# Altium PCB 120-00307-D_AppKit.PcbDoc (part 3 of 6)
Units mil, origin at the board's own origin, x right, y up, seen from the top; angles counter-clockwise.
Board outline 5150 x 3100 mil, 6 copper layers (L1, L2 (GND), L3-SIG, L4-SIG, L5 (PWR), L6), stack 61.956 mil thick; 413 components, 344 nets, 1685 pads, 1021 vias.
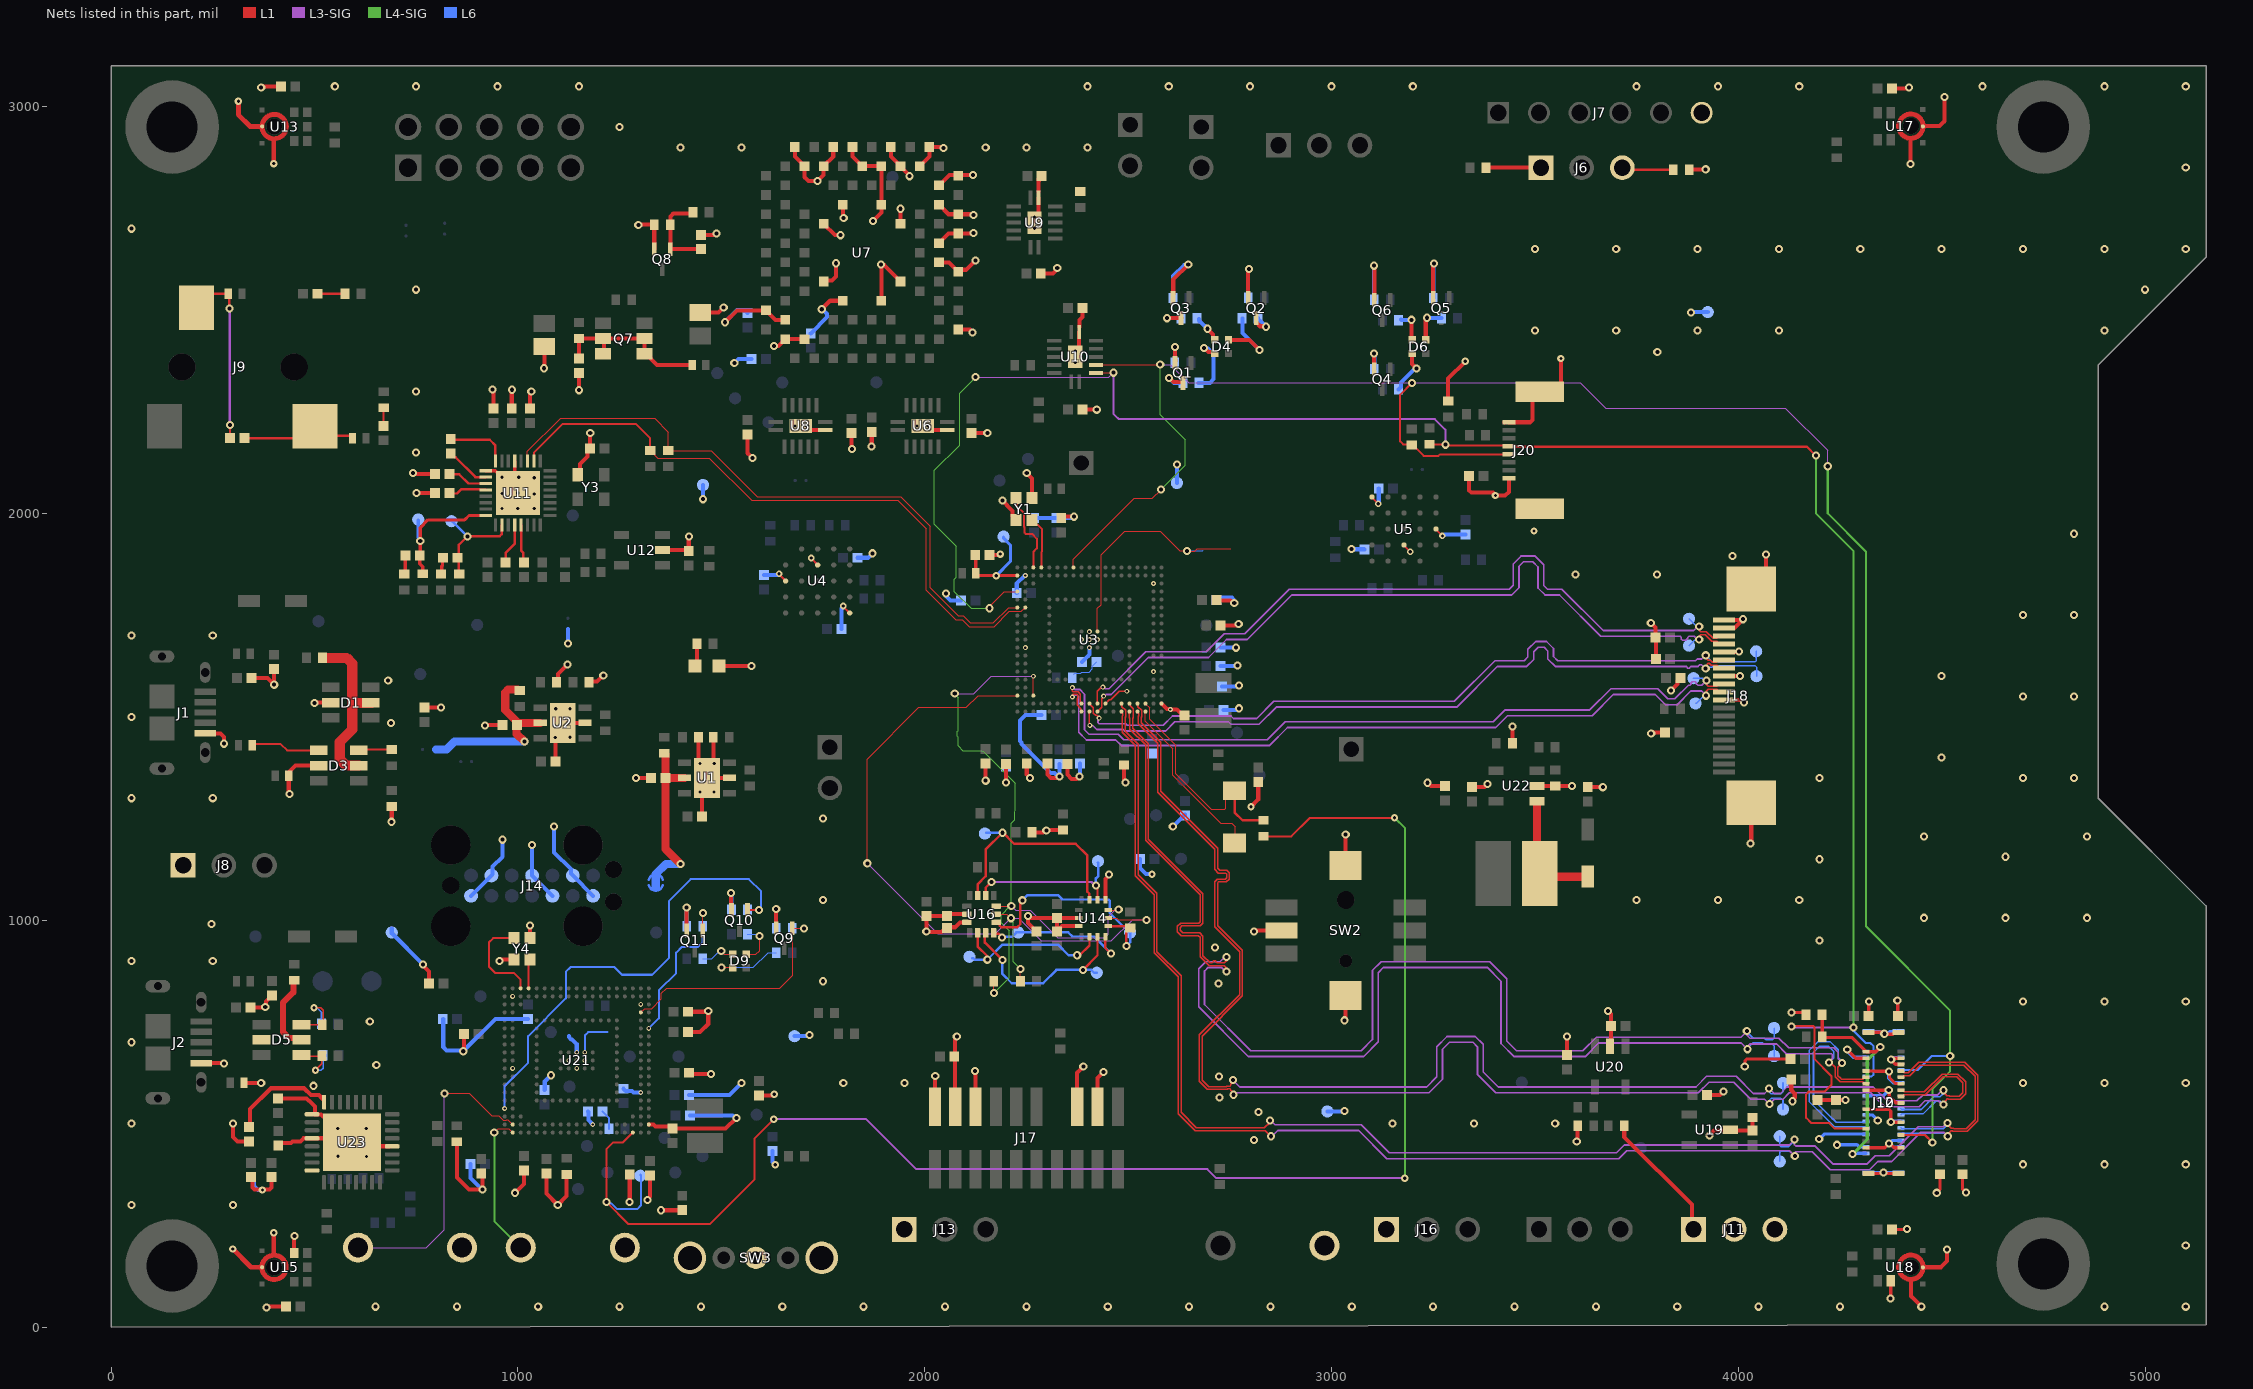
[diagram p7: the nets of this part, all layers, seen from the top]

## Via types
v1: diameter 20, hole 10, L1 to L6, tented both sides, 437 vias
v2: diameter 20, hole 10, L1 to L6, 330 vias
v3: diameter 12, hole 6, L1 to L6, tented both sides, 120 vias
v4: diameter 18, hole 8, L1 to L6, 93 vias
v5: diameter 16, hole 8, L1 to L6, tented both sides, 41 vias

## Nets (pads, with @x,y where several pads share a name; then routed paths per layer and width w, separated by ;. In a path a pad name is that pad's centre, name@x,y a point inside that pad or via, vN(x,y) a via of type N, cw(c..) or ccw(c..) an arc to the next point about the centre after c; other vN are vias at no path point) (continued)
GND: C1.2 C2.1 C3.2 C4.1 C5.1 C6.1 C7.2 C8.2 C9.1 C10.1 C11.1 C12.1 C13.1 C14.1 C15.1 C16.1 C17.1 C18.1 C19.1 C20.1 C21.1 C22.1 C23.1 C24.2 C25.2 C26.2 C27.1 C28.1 C29.1 C30.1 C31.1 C32.1 C33.1 C34.1 C35.1 C36.1 C37.1 C38.1 C39.1 C40.1 C41.1 C42.1 C43.1 C44.2 C45.1 C46.2 C47.1 C48.2 C49.1 C50.1 C51.1 C52.1 C53.1 C54.1 C55.1 C56.2 C57.1 C64.1 C65.1 C66.1 C71.1 C72.1 C73.1 C75.2 C76.1 C77.2 C78.1 C79.2 C80.2 C81.2 C82.2 C83.2 C84.2 C85.1 C86.1 C87.1 C88.1 C89.1 C90.1 C91.1 C92.1 C93.1 C94.1 C95.1 C96.1 C97.1 C98.1 C99.1 C100.1 C101.1 C102.1 C103.1 C104.1 C105.1 C106.1 C107.1 C108.1 C109.2 C110.2 C111.1 C112.1 C113.1 C114.1 C115.1 C116.2 C117.2 C118.2 C119.1 C120.2 C121.1 C122.1 C123.2 C124.2 C125.1 C126.1 C127.1 C128.1 C129.1 C130.1 C131.1 C132.1 C133.1 C134.1 C141.1 D1.2 D2.K D3.2 D5.2 FB3.2 FB5.2 J1.5 J2.5 J7.6 J8.1 J10.2 J10.3 J10.6 J10.9 J10.12 J10.16 J10.19 J10.25 J10.28 J10.31 J10.33 J10.35 J10.36 J10.37 J10.38 J11.2 J11.3 J12.2 J12.3 J12.6 J12.9 J12.12 J12.16 J12.19 J12.25 J12.28 J12.31 J12.33 J12.35 J12.36 J12.37 J12.38 J13.1 J14.2 J14.4 J14.6 J14.8 J14.10 J14.14 J16.1 J17.3 J17.5 J17.15 J17.17 J17.19 J18.10 J18.13 J18.16 J18.19 J18.20 J18.21 J18.22 J20.1 J20.8 J20.9 J20.10 Q1.2 Q2.2 Q3.2 Q4.2 Q5.2 Q6.2 Q8.2 Q9.2 Q10.2 Q11.2 R4.1 R6.1 R10.1 R11.1 R12.2 R15.1 R18.1 R19.1 R22.1 R24.1 R25.1 R36.1 R37.2 R41.1 R44.1 R45.2 R72.1 R74.2 R75.1 R76.1 R81.1 R83.1 R84.1 R88.1 R89.1 R92.2 R101.2 R104.2 S7.1 SW1.2 SW2.5 SW2.SH1 SW2.SH2 SW3.2 SW3.4 SW3.5 SW4.2 SW5.2 TP5.1 TP6.1 TP7.1 TP8.1 TP9.1 TP10.1 U1.2 U1.7 U2.2 U2.7 U3.B2 U3.C18 U3.J10 U3.J11 U3.K9 U3.K10 U3.K11 U3.L2 U3.L10 U3.P18 U3.V12 U3.V19 U4.B3 U4.C1 U4.E5 U5.B3 U5.C1 U5.E5 U6.7 U6.15 U7.A3 U7.A7 U7.A9 U7.A13 U7.A17 U7.B4 U7.B6 U7.B10 U7.B12 U7.B14 U7.B16 U7.C19 U7.D18 U7.F8 U7.F12 U7.F18 U7.G19 U7.H6 U7.H14 U7.J19 U7.K18 U7.M18 U7.N19 U7.P6 U7.P14 U7.T8 U7.T12 U7.U1 U7.V2 U7.W19 U7.Y2 U7.Y4 U8.7 U8.15 U9.7 U9.15 U10.7 U10.15 U11.5 U11.9 U11.33 U12.2 U13.3 U14.1 U14.6 U14.7 U15.2 U15.3 U16.6 U16.7 U17.3 U18.2 U18.3 U19.2 U20.2 U21.B2 U21.C18 U21.J10 U21.J11 U21.K9 U21.K10 U21.K11 U21.L2 U21.L10 U21.P18 U21.V12 U21.V19 U22.2 U23.4 U23.17 U23.20 U23.24 U23.33 Y1.2 Y1.4 Y3.2 Y4.2 Y4.4 | length 18392.9
  L1 w3: U3.J11@2424.68,1709.68 2424.68,1766.68 2434,1776 2434,1786.89 2434.26,1787.16 2434.26,1898.26 2492,1956 2579,1956 2627,1908 v2@2643,1908 ; v2@2647,1907 2664,1907 2670,1913 2752,1913
  L1 w4: U3.V12@2444.37,1532.52 2453.85,1542 2457.63,1542 2478.63,1563 v3(2497,1563)
  L1 w5: v5(1642,1851.47) 1642,1850.26 U4.C1@1658.29,1833.97 ; v5(1721,1890.47) 1721,1889.37 U4.B3@1737.03,1873.34 ; v5(1800,1772.47) 1800,1771 U4.E5@1815.77,1755.23 ; U5.E5@3099.16,2039.9 v5@3114.77,2024.3 ; U5.B3@3178,1921.88 v5@3193.77,1906.11 ; U5.C1@3256.71,1961.23 v5@3272.77,1945.17
  L1 w8: U11.9@921.26,2105.12 944.88,2105.12 v4(961,2089) U11.33@992.13,2057.87 ; U11.5@992.13,2128.74 U11.33@992.13,2057.87 ; v4(1000,2050) U11.33@992.13,2057.87 ; v1(4016,640) 4016.8,640.8 4016.8,654.31 4021.49,659 C92.1@4128.57,659 ; v1(4131,773) 4161.32,773 R75.1@4166.31,768 ; v1(4268,682) 4289.02,660.98 J10.33@4314.17,660.98 ; J10.19@4314.17,440.51 4360.51,440.51 v1(4371,451) ; J10.25@4314.17,535 4370,535 ; J10.28@4314.17,582.24 v1@4367.24,582.24 ; J10.31@4314.17,629.49 4334.51,629.49 4335,629 4370,629 v1(4371,628) ; C87.1@4320.43,765 4321,765.57 v1(4321,800) ; J10.36@4320.67,377.13 4350.88,377.13 4354.75,381 v1@4355,381 ; J10.38@4320.67,724.37 4352.38,724.37 4356.75,720 v1@4358,720 ; v1@4359,720 4380.28,720 4384.65,724.37 J10.37@4393.5,724.37 ; v1@4360.25,380 4363.12,377.13 J10.35@4393.5,377.13 ; 4371,535 4375,531 v1(4375,504) 4375.5,503.5 J10.12@4400,503.5 ; v1@4371,582 4371,567 4386.74,551.26 4399.49,551.26 J10.9@4400,550.75 ; v1@4371,631 4371.56,630.44 4371.56,613.44 4386.62,598.38 4399.61,598.38 J10.6@4400,597.99 ; v1@4373,451 4383.49,440.51 J10.16@4400,440.51 ; v1(4374,70) 4375,71 U18.2@4375,114.02 ; C84.2@4377.72,240 4414,240 v1(4415,241) ; v1(4391,803) 4392.28,801.72 C88.1@4392.28,765 ; J10.3@4400,645.24 4399.55,645.69 4386.31,645.69 4376,656 v1(4376,658) 4378.81,660.81 4399.82,660.81 J10.2@4400,660.98 ; v1(4488,330) 4496,338 C86.1@4496,375.57 ; C85.1@4551,375.57 4551,340 v1(4560,331)
  L1 w10: J2.5@221.3,648.82 277.18,648.82 v1(278,648) ; J1.5@231.3,1459.45 268.55,1459.45 278,1450 v1(278,1434) ; v1@299,500 300,499 300,467 311,456 C131.1@339,456 ; FB5.2@326.73,600 v1(369,600) ; C8.2@342.72,785 343.72,786 378,786 v1(379,787) 380.91,788.91 380.91,800.2 C7.2@396,815.28 ; C133.1@344,371 348,367 348,343 352.47,338.53 370.47,338.53 v4(372,337) 373.53,338.53 389.67,338.53 394,342.86 C134.1@394,368.28 ; C3.2@345,1595 385,1595 v1@400,1580 ; v1(369,3047) 372,3050 C75.2@417.28,3050 ; v1(382,48) 384,50 C79.2@429.57,50 ; C1.2@400,1617.28 v1@400,1580 ; v1(401,1579) v1@400,1580 ; C129.1@410,561.72 480.9,561.72 485.62,557 486,557 501,542 U23.17@501,523.34 ; C130.1@416,445 416,449.8 418.2,452 442,452 446.49,456.49 465.49,456.49 473,464 U23.20@493.93,464 540,464 U23.33@542,466 ; v1(439,1310) 436.73,1312.27 FB3.2@436.73,1355 438.62,1356.89 438.62,1365.75 452.87,1380 D3.2@510.79,1380 ; U15.2@450,180.87 U15.2@450,182 450,223 v1(451,224) ; U23.17@499.86,523.06 500.15,522.77 516.23,522.77 520.94,518.06 528.94,518.06 U23.33@530,517 ; v1(500,1534) 501,1535 D1.2@540,1535 ; U23.33@656,444 656.32,444.32 U23.4@685,444.32 ; v1(689,1242) 690,1243 R12.2@690,1279.68 ; v1(742,2099) 744,2097 C71.1@796.28,2097 ; v1(751,2050) C72.1@796.28,2050 ; v1@770,891 768.91,889.91 768.91,886.38 781.28,874.01 C109.2@781.28,844 ; C9.1@770,1522.72 810.72,1522.72 v1(811,1523) ; R104.2@850,455.31 850,368 880,338 910,338 v1@912,340 ; v1(865.72,678) 867.28,679.57 C102.1@867.28,720 ; C111.1@910,377.28 913,374.28 v1@913,340 ; v1(919,1479) 920,1479 921,1480 C5.1@962.28,1480 ; v1(938,2305) 940,2303 C65.1@940,2257.72 ; v1(955,900) 958.43,903.43 Y4.4@990.32,903.43 ; C64.1@985,2257.72 985,2303 v1(986,2304) ; v1(993,330) 1015,352 C108.1@1015,385 ; Y4.2@1029.68,956.57 1029.84,956.73 1029.84,986.84 v1(1030,987) ; C66.1@1030,2257.72 1030,2297 v1(1033,2300) ; v1(1064,2357) 1065,2358 C54.1@1065,2410 ; C99.1@1070,377.28 1070,328 v1(1098,300) 1120,322 R76.1@1120,375.32 ; v4(1092,1449) U2.7@1092.72,1449.72 ; C6.1@1092.72,1390 U2.7@1092.72,1449.72 ; R10.1@1094.68,1585 1098.76,1589.07 1098.76,1605.76 v1(1122,1629) ; U2.7@1116,1483 1118,1485 U2.2@1165,1485 ; Y3.2@1147.52,2095.51 1152.39,2100.38 1152.39,2121.39 1171.33,2140.33 1171.33,2154.05 C57.1@1177.28,2160 1177.28,2197.28 v1(1178,2198) ; v1(1150,2303) C53.1@1150,2345 ; R11.1@1174.68,1585 1176.34,1586.65 1194.65,1586.65 v1(1210,1602) ; v1(1274,307) 1275,308 C105.1@1275,375 ; v1(1290,1350) C2.1@1327.28,1350 ; v1(1296,2709) 1297,2710 R44.1@1335.32,2710 Q8.2@1335.32,2649.57 ; v1(1318.5,312) 1318.5,314.71 1325,321.21 C115.1@1325,372.28 ; U21.V19@1321.85,497.84 1333.16,497.84 1338,493 1380,493 1385.28,487.72 1510.72,487.72 v1(1537,514) ; U12.2@1355.25,1910 1417.72,1910 C73.1@1420,1907.72 1420,1942 v1(1421,1943) ; Q11.2@1415,975 v1(1415,1031) ; C103.1@1417.72,725 1448,725 1468,745 v1(1468,777) 1465.29,777 1463.29,775 C107.1@1417.72,775 ; C100.1@1420.43,625 1423.43,622 v1(1475,622) ; R4.1@1444.37,1450 1444.37,1389.63 U1.7@1448.5,1385.5 ; v4(1448,1315) U1.7@1452.72,1319.72 ; v4(1448,1385) 1464,1369 1464,1351 U1.7@1465,1350 ; C52.1@1448,2493.57 1493.57,2493.57 v1(1506,2506) ; C125.1@1450,2685 1485,2685 v1(1488,2688) ; C4.1@1452.72,1255 U1.7@1452.72,1319.72 ; R6.1@1480.32,1450 1481,1449.32 U1.7@1481,1366 ; v4(1483,1385) 1483,1368 U1.7@1481,1366 ; D2.K@1494.53,1625 v1(1574,1625) ; v1(1509,2470) 1538.29,2499.29 U7.U1@1610,2499.29 1633.62,2475.67 U7.V2@1657.24,2475.67 ; U1.2@1520,1350 1491.5,1350 1481,1360.5 U1.7@1481,1366 ; v1(1524,1067) 1524,1041.69 1524.09,1041.6 1524.09,1025.91 Q10.2@1525,1025 ; C46.2@1565,2194.57 1565,2148 v1(1577,2136) ; C128.1@1593,569.28 1627.28,569.28 v4(1630,572) ; v2(1630,2412) 1640.82,2412 U7.Y2@1657.24,2428.43 U7.Y4@1704.49,2428.43 ; Q9.2@1635,980 v1(1635,1028) ; U7.A3@1680.87,2900.87 1680.87,2877.24 U7.B4@1704.49,2853.62 1704.49,2826.51 1714,2817 v1(1737,2817) 1751.73,2831.73 U7.B6@1751.73,2853.62 1775.35,2877.24 U7.A7@1775.35,2900.87 ; U8.15@1695,2215 1704.84,2205.16 U8.7@1756.02,2205.16 ; v1(1747,2502) 1767.91,2522.91 U7.T8@1798.98,2522.91 ; U7.P6@1751.73,2570.16 1754.26,2572.69 1772.69,2572.69 1782,2582 v1(1782,2615) ; U7.H6@1751.73,2711.89 1779.62,2684 v1(1793,2684) ; U7.F8@1798.98,2759.13 1798.98,2728.02 v1(1801,2726) ; C45.1@1820,2197.28 1820,2159 v1(1821,2158) ; U7.A9@1822.6,2900.87 1822.6,2877.24 U7.B10@1846.22,2853.62 U7.B12@1893.46,2853.62 U7.F12@1893.46,2759.13 1893.46,2739.46 v1(1873,2719) ; v1(1869,2165) 1870,2166 C44.2@1870,2200 ; v1(1893,2612) v1@1893.46,2611.54 ; U7.T12@1893.46,2522.91 v1@1893.46,2611.54 ; U7.A13@1917.09,2900.87 1917.09,2877.24 1963,2831.33 v1(1963,2829) ; U7.P14@1940.71,2570.16 1900.78,2610.09 1894.91,2610.09 v1@1893.46,2611.54 ; U7.H14@1940.71,2711.89 1940.71,2748.71 v1(1941,2749) ; U7.B16@1987.95,2853.62 2011.57,2877.24 U7.A17@2011.57,2900.87 2043.13,2900.87 v1(2046,2898) ; U6.15@1995,2215 2004.84,2205.16 U6.7@2056.02,2205.16 ; J17.19@2025,541.77 2025,616 v1(2026,617) ; U7.M18@2035.2,2617.4 2035.93,2616.67 2059.55,2616.67 2075.63,2600.59 U7.N19@2082.44,2593.78 2087.69,2599.03 2102.03,2599.03 v1(2125,2622) ; U7.K18@2035.2,2664.65 2058.82,2688.27 U7.J19@2082.44,2688.27 2119.27,2688.27 v1(2120,2689) ; U7.F18@2035.2,2759.13 2058.82,2735.51 U7.G19@2082.44,2735.51 2118.49,2735.51 v1(2120,2734) ; U7.D18@2035.2,2806.38 2060.82,2832 v1(2119,2832) ; J17.17@2075,541.77 2075,710 v1(2079,714) ; U7.W19@2082.44,2452.05 2110.95,2452.05 v1(2118,2445) ; U16.7@2103.98,995.32 2102.81,994.15 2086.43,994.15 2075,982.72 2057.28,982.72 C80.2@2055,980.43 2047.8,973.23 2044.17,973.23 2041.94,971 2005,971 v1(2004,972) 2005,973 C82.2@2005,1010 C81.2@2055,1010 2060,1015 U16.6@2103.98,1015 ; C43.1@2115,2197.28 2153.28,2197.28 v1(2154,2198) ; v1(2124,629) 2125,628 J17.15@2125,541.77 ; C28.1@2149.86,1385.14 2149.86,1343.14 v1(2150,1343) ; C24.2@2159.72,1898 2184,1898 v4(2186,1900) ; v2(2191,2032) 2202.54,2020.46 2202.54,2019.31 2216,2005.84 2216,1992.55 Y1.4@2224.31,1984.24 ; v1(2200,1339) C21.1@2200,1384.28 ; C15.1@2251,1385.28 2251,1358 v1(2259,1350) ; v2(2251,2099) 2263.68,2086.32 Y1.2@2263.68,2037.39 ; R101.2@2263.69,1216 2291.29,1216 2296.29,1221 v1(2299,1221) 2299.63,1221.63 R36.1@2340,1221.63 ; C76.1@2275,972.72 2254,993.72 v1(2254,1010) 2259,1005 C77.2@2325,1005 ; U9.7@2279.84,2776.02 2279.84,2718.16 U9.15@2281,2717 ; U9.7@2280,2791 2280,2816.94 2280.51,2817.45 2280.51,2822.8 C47.1@2287.72,2830 ; C48.2@2285.43,2589.43 C48.2@2286,2590 ; C48.2@2285.43,2590 C48.2@2286,2590 ; C48.2@2288,2592 C48.2@2286,2590 ; C12.1@2302,1385.28 2302,1358 2310,1350 2325.11,1350 2328.61,1353.5 v1(2331.32,1353.5) ; v1(2326,2603) 2326,2600.86 2315.14,2590 C48.2@2286,2590 ; C20.1@2335.81,1988.53 2339.28,1992 v2(2367,1992) ; C13.1@2351,1384.57 2351,1358 2361.32,1347.68 2372.97,1347.68 2378.29,1353 v1(2381,1353) ; J17.5@2375,541.77 2375,625 v1(2390,640) ; U10.15@2379,2401 2379.84,2401.84 U10.7@2379.84,2446.02 ; U14.7@2379.07,985.32 2337.6,985.32 C78.1@2325,972.72 C77.2@2325,1005 ; U14.6@2379.07,1005 C77.2@2325,1005 ; U10.7@2380.12,2458.74 2380.12,2462.06 2381,2462.94 2381,2476 2387.72,2482.72 C55.1@2387.72,2505 ; C56.2@2387.72,2255 v1(2423,2255) ; J17.3@2425,541.77 2425,612 v1(2440,627) ; U14.1@2444.53,1050.77 2444.53,1101.14 2453,1109.61 v1(2453,1112) ; R37.2@2490,1381.31 2490,1345.71 2494,1341.71 v1(2494,1339) ; U3.V19@2582.16,1532.52 2595.68,1519 v3@2604,1519 ; v3(2604,1518) 2619.72,1518 C11.1@2635,1502.72 ; Q3.2@2610,2540 2611,2541 2611,2575 v1(2648,2612) ; v1(2615,2409) 2615,2377 Q1.2@2616,2376 ; C22.1@2721,1786 2752.29,1786 2758.29,1780 v1(2761,1780) ; C34.1@2727.72,1725 2769,1725 v1(2772,1728) ; Q2.2@2795,2538 2795,2596.29 2797,2598.29 v1(2797,2601) ; v4(2802,1279) 2820,1297 C26.2@2820,1340.28 ; v1(2810,972) 2812.8,974.8 SW2.5@2877.52,974.8 ; v1(3032,754) 3035,757 SW2.SH1@3035,815.35 ; SW2.SH2@3035,1134.25 v1(3035,1211) ; Q4.2@3105,2361 v1(3105,2393) ; v1(3105,2609) 3105.31,2608.68 Q6.2@3105.31,2524.57 ; v1(3236,1338) 3244.28,1329.72 C122.1@3279,1329.72 ; Q5.2@3250,2539 3250,2609.29 3252,2611.29 v1(3252,2614) ; R92.2@3287,2276.69 3287,2332 v4(3329,2374) ; C124.2@3338.28,2092 3338.28,2056.86 3344.14,2051 3397.14,2051 3403,2045.14 v4(3403,2044) ; C123.2@3345,1327.72 3376.72,1327.72 v1(3384,1335) ; v4@3401,2044 v4(3403,2044) ; J20.8@3426,2224 J20.8@3426,2224.57 ; J20.1@3436.21,2086.4 3436.21,2053.21 3427,2044 v4(3403,2044) ; J20.8@3436.21,2224.2 3488.2,2224.2 3494.06,2230.05 3494.06,2278.41 3513.65,2298 J20.10@3526,2298 ; R88.1@3444.69,1435 3445,1435.31 v1(3445,1476) ; U22.2@3505.25,1330 R89.1@3550,1330 v1(3591,1330) ; J20.10@3544.14,2299 3564,2318.86 v4(3564,2381) ; C96.1@3579,668.72 v1(3579,714) ; v1(3603,456) 3605.31,458.31 R74.2@3605.31,495 ; C121.1@3630,1327.72 3630.72,1327 v1(3667,1327) ; v1(3680,777) 3687.28,769.72 C95.1@3687.28,740 ; U20.2@3685,690.25 3687,692.25 C95.1@3687,740 ; v2(3785,1731) 3796.28,1719.72 C117.2@3796.28,1695 3797.28,1694 C118.2@3797.28,1642 ; v1(3786,1459) 3788,1461 C120.2@3820.28,1461 ; v1@3799.09,2395.09 v1(3801,2397) ; v1(3835,1565) 3850.51,1580.51 3850.51,1587.8 C119.1@3857.72,1595 ; R41.1@3879.69,2845 3919,2845 v1(3920,2846) ; C94.1@3922.72,570 3955,570 v1(3964,579) ; v1(3929,471) 3940.72,482.72 C93.1@4035,482.72 ; J18.10@3965,1541.57 4007.43,1541.57 v1(4014,1535) ; J18.13@3965,1600.63 4003.37,1600.63 v1(4004,1600) ; J18.16@3965,1659.68 4000.69,1659.68 v1(4002,1661) ; J18.19@3965,1718.74 3990.74,1718.74 v1@4010.43,1738.43 ; J18.20@3965,1738.43 v1@4010.43,1738.43 ; v1(4012,1740) v1@4010.43,1738.43 ; v1@4030,1192 4030.29,1192 4031.93,1193.64 J18.21@4031.93,1288.66 ; C93.1@4035,486 R72.1@4035,515 ; J18.22@4061,1816.47 4068,1823.47 v1(4068,1899) ; C91.1@4130.28,608 4130.28,582.72 4138.86,574.14 4138.86,563.56 4133,557.71 v1(4133,555) ; C89.1@4195,557.72 C90.1@4240,557.72 4262.72,557.72 4263,558 v2(4263.51,558) ; C83.2@4377.72,3045 4418,3045 v1(4420,3047) ; v1(4423,2859) 4423.65,2859.65 4423.65,2917.63 4429.5,2923.49 4436.1,2923.49 4452.79,2940.19 4452.79,2951.14 U17.3@4453.64,2951.99 ; v1(4450,50) 4424.29,75.71 4424.29,112.65 4430.15,118.51 4436.1,118.51 4452.79,135.2 4452.79,145.51 4454.29,147.01 4498.01,147.01 4513,162 v1(4513,191) ; U17.3@4454.29,2951.99 4494.8,2951.99 4507,2964.19 v1(4507,3024) ; U2.7@1092.72,1449.72 1092.72,1467.72 U2.7@1110,1485 1110,1467 U2.7@1092.72,1449.72 ; U1.7@1452.72,1319.72 1465,1332 U1.7@1465,1350 ; U1.7@1452.72,1319.72 1452.72,1337.72 U1.7@1465,1350 ; U1.7@1465,1350 U1.7@1481,1366
  L1 w12: v4(299,192) 344.03,146.97 370.71,146.97 U15.3@371.17,146.97 ; v4(313,3013) 313,2980 341.59,2951.41 U13.3@371.46,2951.41 U13.3@371.01,2951.86 ; 400,178 v4(400,232) ; v4(400,2860) 399.99,2921.02 399.99,2921.22 ; v2(1352,287) 1352.14,287.14 1403.86,287.14 C141.1@1404,287.28
  L6 w3: v2@2643,1908 v2(2645,1908) 2683,1908 2685,1910
  L6 w5: v3(1164.37,675) 1164.69,675.32 1164.69,715 1164.69,716.67 1173.01,725 1220,725
  L6 w8: v1(4199,462) 4211.25,474.25 J12.31@4314.17,474.25 ; v1(4243,448) 4292,448 4297.24,442.76 J12.33@4314.17,442.76 ; v1(4268,682) 4270.3,679.7 4270.3,674.95 4282.02,663.23 J12.19@4314.17,663.23 ; J12.28@4314.17,521.5 4329.5,521.5 v1(4343,508) ; J12.25@4314.17,568.74 4356.74,568.74 v1@4370,582 ; J12.38@4320.67,379.37 v1@4357,379.37 ; J12.36@4320.67,726.61 4346.39,726.61 4352,721 v1(4359,721) 4367,721 4372.24,726.24 4388.24,726.24 J12.35@4389,727 ; v1(4357,380) v1@4357,379.37 ; v1@4369,451 v1(4371,451) 4371.09,451 4378.59,458.5 J12.3@4400,458.5 ; v1@4369,629 4369.56,628.44 4369.56,611.44 4380.76,600.24 J12.12@4400,600.24 ; v1@4372,451 4372.99,451 4381.23,442.76 J12.2@4400,442.76 ; v1@4372,585 4372,566 4385.01,552.99 J12.9@4400,552.99 ; v1(4375,504) 4376.75,505.75 J12.6@4400,505.75 ; v1(4376,658) 4379.25,658 4384.02,662.78 4399.55,662.78 J12.16@4400,663.23 ; J12.37@4391,378 4389.63,379.37 v1@4357,379.37
  L6 w10: C132.1@344,368.28 351.2,361.08 351.2,346.8 361,337 v4(372,337) ; TP9.1@690,980 TP9.1@690,970 690,968 v1(767,891) ; C110.2@816.57,757 816.57,688.43 825,680 856.65,680 856.73,679.91 863.8,679.91 v1(865.72,678) 945,757.28 C101.1@1025,757.28 ; C106.1@883.28,401 883.28,366.72 v1@914,336 ; J14.14@885,1060 J14.2@935,1110 938.13,1113.13 938.13,1132.13 962,1156 v1(962,1198) ; v1(1035,1185) J14.4@1035,1110 J14.10@1085,1060 ; C104.1@1065,582.72 1066.06,583.78 1066.06,604.06 v1(1081,619) ; v1(1089,1230) 1089,1167 1130.41,1125.59 1130.41,1114.59 J14.6@1135,1110 J14.8@1185,1060 ; v1(1123,1680) S7.1@1123,1715.7 ; 1125.32,715 1125.32,713.03 1131.14,707.2 1133.11,707.2 1144.68,695.63 v3(1144.68,675) ; C114.1@1172.28,530 1173.24,529.05 1173.24,508.65 v3(1184.05,497.84) ; C98.1@1260,585.72 1265.17,580.55 1280.45,580.55 1284,577 1300.33,577 1300.37,576.96 1301.78,576.96 v3(1302.16,576.58) ; R84.1@1415,985.43 v1(1415,1031) ; C112.1@1420.43,570 1520,570 v1(1550,600) ; C113.1@1422.72,520 1528.29,520 1534.29,514 v1(1537,514) ; v1(1455,2035) TP8.1@1455,2070 ; v1(1509,2470) 1539,2500 1551.94,2500 1552.02,2499.92 1557.8,2499.92 C50.1@1565,2492.72 ; v1(1524,1067) 1525,1066 R83.1@1525,1025.43 ; v1(1532,2370) 1542,2380 C49.1@1574.57,2380 ; C40.1@1605,1848.72 1637.62,1848.72 1640.38,1851.47 v5(1642,1851.47) ; C127.1@1626,432.28 1626,406 v4(1633,399) ; R81.1@1635,980.43 v1(1635,1028) ; TP7.1@1680,715 1714,715 v1(1717,718) ; C51.1@1720,2442.72 1759.86,2482.57 1759.86,2490.86 1748.72,2502 v1(1747,2502) ; C39.1@1795.43,1716 1795.43,1766.28 1800,1770.84 v5(1800,1772.47) ; C37.1@1835,1891 1861,1891 v2(1872,1902) ; v2(2052,1803) 2053.91,1801.09 2053.91,1796.09 2064,1786 C17.1@2089.28,1786 ; v2@2191,2029.29 v2(2191,2032) ; v1(2200,1339) C23.1@2200,1378.38 ; C19.1@2226.28,1804 2226.28,1827.28 2246.1,1847.1 2246.6,1847.1 2247,1847.5 v3@2247,1848 ; C25.2@2269,1988.53 C16.1@2324,1988.53 2363.53,1988.53 v2(2367,1992) ; C126.1@2287.28,1505 2248,1505 2234.5,1491.5 2234.5,1440.49 2238.2,1436.79 2238.2,1432.8 2309,1362 2319,1362 2325.59,1355.41 2326.7,1355.41 2330,1352.11 v1@2330,1351 ; v1(2331.32,1353.5) C31.1@2331.32,1384.57 ; v1(2381,1353) 2382,1354 C30.1@2382,1385.57 ; C35.1@2387.28,1635 2402.51,1650.23 2402.51,1650.52 2405,1653.01 v3(2405,1670.32) ; C27.1@2529.28,1151 2529.28,1128.72 2544,1114 2558,1114 v4(2559,1113) ; v1(2610,1230) C36.1@2640,1260 ; R19.1@2610.31,2529.57 2610.31,2583.31 2637.09,2610.09 2646.09,2610.09 v1(2648,2612) ; R15.1@2615,2370 v1(2615,2409) ; TP10.1@2620,2075 v1(2620,2120) ; C18.1@2714,1793 2755,1793 2759.09,1788.91 2759.09,1781.91 v1(2761,1780) v1@2763.71,1780 ; C10.1@2727.72,1625 2768,1625 v1(2769,1626) ; C29.1@2727.72,1670 v1(2765,1670) ; C14.1@2730.43,1575 2768.29,1575 2770.29,1577 v2(2773,1577) ; C32.1@2734.72,1517 2766.29,1517 2770.29,1521 v1(2773,1521) ; R18.1@2795.31,2530 2795.31,2599.32 v1(2797,2601) ; TP5.1@2990,530 3031,530 v1(3032,531) ; v1(3049.5,1913) 3050.5,1912 3080.28,1912 C38.1@3081.28,1911 ; v1(3105,2393) 3105.31,2392.68 R22.1@3105.31,2355 ; R25.1@3105,2523 v1(3105,2609) ; v5(3114.77,2023.77) 3114.77,2025.39 3116.28,2026.91 C41.1@3116.28,2061 ; R24.1@3250.31,2529.57 3250.31,2612.31 v1(3252,2614) ; v5@3272,1945 3274.62,1945 3277.91,1948.28 C42.1@3329,1948.28 ; v1(3884,2494) 3885,2495 TP6.1@3925,2495
  other v1: 650,50 850,50 1050,50 1250,50 1450,50 1650,50 1850,50 2050,50 2250,50 2450,50 2650,50 2850,50 3050,50 3250,50 3450,50 3650,50 3850,50 4050,50 4250,50 4900,50 5100,50 5100,200 50,300 300,300 913,338 4700,400 4900,400 5100,400 2809.97,459.56 50,500 300,500 3150,500 3350,500 3550,500 2820.97,528.56 2724.97,564.56 4370,583 498,593 1800,600 1950,600 4700,600 4900,600 5100,600 2723.97,615.56 652,644 50,700 636,751 4700,800 4900,800 5100,800 2721.97,844.56 1750,850 50,900 250,900 2714,933 4200,950 247,991 4457,1006 4657,1006 4857,1006 1750,1050 3750,1050 3950,1050 4150,1050 4200,1150 4657,1156 4030,1189 4457,1206 4857,1206 1750,1250 50,1300 250,1300 4200,1350 4700,1350 4825,1350 4500,1400 688.21,1484.77 50,1500 4700,1550 4825,1550 681.21,1589.77 4500,1600 50,1700 250,1700 4700,1750 4825,1750 3600,1850 3800,1850 3986,1895 4825,1950 750,2150 750,2300 3500,2450 3700,2450 3900,2450 4100,2450 4900,2450 750,2550 5000,2550 3500,2650 3700,2650 3900,2650 4100,2650 4300,2650 4500,2650 4700,2650 4900,2650 5100,2650 50,2700 5100,2850 1400,2900 1550,2900 2150,2900 2250,2900 2400,2900 1250,2950 550,3050 750,3050 950,3050 1150,3050 2400,3050 2600,3050 2800,3050 3000,3050 3200,3050 3750,3050 3950,3050 4150,3050 4600,3050 4900,3050 5100,3050
  other v3: 987.2,635.63 1144.68,635.63 1125,655.32 1144.68,655.32 1164.37,655.32 1302.16,793.11 987.2,812.8 2562.48,1611.26 2247.52,1670.32 2385.32,1690 2405,1690 2424.68,1690 2405,1709.68 2562.48,1827.8 2247.52,1847.48
  other v4: 628,419 558,420 557,488 627,488 1482,1315 1128,1450 1093,1520 1128,1520 3498,1957 961,2012 1000,2012 1040,2012 1040,2048 961,2049 1040,2088 1002,2089 1681,2215 1710,2215 1981,2215 2009,2215 2370,2371 2370,2399 2270,2701 2270,2729
  other v5: 3193.77,1905.77 3272.77,1944.77
HEADP_L: C60.1 FB12.2 J9.2 | length 229.5
  L1 w6: C60.1@327.72,2185 481,2185 J9.2@484,2182 ; J9.2@525,2191 589.38,2191 593.27,2187.11 FB12.2@593.27,2185
HEADP_R: C60.2 FB11.2 J9.3 | length 422.2
  L1 w6: J9.3@218,2541 219,2540 FB11.2@288.27,2540 ; v2(291,2504) FB11.2@291,2536 ; v2(292,2217) 292.28,2216.72 C60.2@292.28,2185
  L3-SIG w6: v2(291,2504) 292,2503 v2(292,2217)
HFXO_N: U3.A3 Y1.3 | length 204.6
  L1 w5: Y1.3@2224.31,2037.39 2226.82,2034.88 2226.82,2018.05 2244.41,2000.47 2244.41,1967.19 2244.91,1966.69 2244.91,1953.09 2248.06,1949.94 2263.94,1949.94 2276,1937.89 2276,1914 2267.2,1905.2 U3.A3@2267.2,1867.16
HFXO_N_J: U21.A3 Y4.3 | length 238.4
  L1 w5: Y4.3@990.32,956.57 989.74,956 939,956 929,946 929,886 945,870 991,870 1006.89,854.11 U21.A3@1006.89,832.48
HFXO_P: U3.A4 Y1.1 | length 130.2
  L1 w5: Y1.1@2263.68,1984.24 2263.68,1983.25 2274.96,1971.97 2278.03,1971.97 2289,1961 2289,1907 2286.89,1904.89 U3.A4@2286.89,1867.16
HFXO_P_J: U21.A4 Y4.1 | length 72.2
  L1 w5: U21.A4@1026.57,832.48 1026.57,900.32 Y4.1@1029.68,903.43
I2C_CL_SCL: R52.2 U3.F2 U11.2 | length 1591
  L1 w3: R52.2@1325,2154.69 1326.97,2154.69 1336.3,2145.36 1336.3,2143.39 1343.68,2136 1471,2136 1575,2032 1934,2032 2004,1962 2004,1811 2076,1739 2093,1739 2110,1722 2171,1722 2208,1759 2237.78,1759 U3.F2@2247.52,1768.74
  L1 w5: U11.2@1039.37,2128.74 1039.37,2149.37 1110,2220 1290,2220 1325,2185 R52.2@1325,2154.69
I2C_CL_SDA: R53.2 U3.F1 U11.3 | length 1600.7
  L1 w3: U11.3@1023.62,2128.74 1023.62,2152.62 1105,2234 1336,2234 1370,2200 R53.2@1370,2154.69 1475.31,2154.69 1589,2041 1941,2041 2014,1968 2014,1817.08 2083.08,1748 2095,1748 2112,1731 2169,1731 2206.74,1768.74 U3.F1@2227.84,1768.74
I2C_FB_SCL: J10.14 J12.14 J20.4 R48.2 U3.A8 U10.3 | length 5029
  L1 w3: U3.A8@2365.63,1867.16 2365.63,1887.63 2515,2037 2560,2037 2581,2058 v2(2581,2059) ; U10.3@2427,2366 v2(2579,2366)
  L1 w5: R48.2@3196,2170 3176,2170 3169,2177 3169,2292 v2(3198,2321) ; R48.2@3206,2162 3206,2161.28 3207.3,2159.99 3208.01,2159.99 3226.5,2141.5 3263,2141.5 3266.96,2145.46 3427.46,2145.46 J20.4@3429,2147 ; J10.14@4400,472.01 4458.99,472.01 v2(4477,454)
  L3-SIG w3: v2(2579,2366) 2604,2366 2649,2321 v2(3198,2321) 3612,2321 3674,2259 4116,2259 4220,2155 v2(4220,2116)
  L4-SIG w3: v2(2579,2366) 2579,2243 2641,2181 2641,2119 v2(2581,2059)
  L4-SIG w5: v2(4220,2116) 4220,2000 4314,1906 4314,985 4521,778 v2(4521,666) 4521,629 4477,585 v2(4477,454)
  L6 w5: J12.14@4400,631.73 4440.73,631.73 4475,666 v2(4521,666)
I2C_FB_SDA: J10.22 J12.22 J20.5 R49.2 U3.D1 U10.2 | length 5365.7
  L1 w3: v2(2159,1767) 2159,1771 2196.11,1808.11 U3.D1@2227.84,1808.11 ; U10.2@2421.18,2345.63 2463.63,2345.63 v2(2464,2346)
  L1 w5: R49.2@3241,2170.31 3242.31,2169 v2(3280,2169) 3283,2169 v2@3284,2168 ; v2@3284,2167.07 3433.09,2167.07 3436.21,2163.94 4169.06,2163.94 v2(4191,2142) ; v2(4131,739) 4132,740 4184,740 4187,737 4187,659 4229,617 4229,595 4213,579 4174,579 4167,572 4167,514 4180,501 4224,501 4237.24,487.76 J10.22@4314.17,487.76
  L3-SIG w3: v2(2125,2335) 2453,2335 v2(2464,2346)
  L3-SIG w5: v2(2464,2346) 2464,2245 2475.02,2233.98 2477,2232 3254,2232 3280,2206 v2(3280,2169) ; v2@4132,739 4135.06,739 4138.06,736 v2(4283,736)
  L4-SIG w3: v2(2125,2335) 2086,2296 2086,2168 2024,2106 2024,1973 2078,1919 2078,1843 2073,1838 2073,1808 2114,1767 v2(2159,1767)
  L4-SIG w5: v2(4191,2142) 4191,2000 4283,1908 v2(4283,736)
  L6 w5: v2(4283,736) 4283,729 4314,698 4325,698 4332,691 4332,620 4327.98,615.98 J12.22@4314.17,615.98
I3C_SCL: R50.2 U3.U1 U14.13 U16.13 | length 1808.7
  L1 w3: v2(1859,1140) 1859,1396 1986,1523 2102,1523 2131.2,1552.2 U3.U1@2227.84,1552.2 ; U16.13@2176.02,1015 2202,1015 v2(2212,1005) ; R50.2@2235.31,850 2235.31,879.31 v2(2236,880) ; U14.13@2450.93,1005 2472,1005 2476,1001 v2(2545,1001)
  L3-SIG w3: v2(1859,1140) 2032,967 2174,967 v2(2212,1005) 2231,1005 2287,949 2459,949 2511,1001 v2(2545,1001)
  L4-SIG w3: v2(2212,1005) 2212,1000.74 2218,994.74 2218,898 v2(2236,880)
I3C_SDA: R51.2 U3.U3 U14.14 U16.14 | length 1569.1
  L1 w3: R51.2@2169.69,850 2169.69,821.31 v2(2170,821) ; U16.14@2176.02,1034.68 2212.68,1034.68 v2(2213,1035) ; v3(2267.1,1599.9) 2267.2,1599.8 U3.U3@2267.2,1552.2 ; U14.14@2450.93,1024.68 2475.68,1024.68 v2(2477,1026)
  L3-SIG w3: v2(2074,1557) 2121,1557 2163.9,1599.9 v3(2267.1,1599.9) ; v2(2213,1035) 2223.5,1024.5 2260.01,1024.5 2268.5,1016.01 2268.5,1015.5 2327,957 2442.3,957 2450.93,965.63 2450.93,1008.93 2468,1026 v2(2477,1026)
  L4-SIG w3: v2(2074,1557) 2074,1554.98 2082,1546.98 2082,1465.51 2080.5,1464.01 2080.5,1451.99 2082,1450.49 2082,1429 2094,1417 2142,1417 2144,1415 2144.51,1415 2223,1336.51 2223,1269 2221,1267 2221,1247 2213,1239 v2(2213,1035) 2211,1035 2188,1012 2188,994 2208,974 2208,859 v2(2170,821)
IMU_2: TP31.1 U14.2 U16.2 | length 395.9
  L1 w6: U16.2@2149.84,1060.87 2149.84,1079.84 v2(2164,1094) ; v2(2421,1085) 2424.84,1081.16 U14.2@2424.84,1050.77
  L3-SIG w6: v2(2164,1094) 2410.49,1094 2420.49,1084 v2@2421,1084
  L6 w6: v2(2421,1085) 2421,1103 2427,1109 2427,1141 TP31.1@2426,1142
IMU_3: TP32.1 U14.3 U16.3 | length 564.1
  L1 w6: U16.3@2130.16,1060.87 2130.16,1088.16 2150,1108 2150,1174 v2(2191,1215) ; v2@2190,1218 2220,1188 2371,1188 2400,1159 2400,1070 2404.7,1065.3 2404.7,1051.23 U14.3@2405.16,1050.77
  L6 w6: TP32.1@2151,1215 v2(2191,1215)
IMU_10: TP34.1 U14.10 U16.10 | length 467
  L1 w6: U16.10@2148,964 2148,945 v2(2191,902) ; v2(2389,878) 2424.84,913.84 U14.10@2424.84,959.23
  L6 w6: v2(2191,902) 2191,868 2214,845 2291,845 2324,878 v2(2389,878) ; v2@2390,878 2409.51,878 2416.51,871 TP34.1@2423,871
IMU_11: TP35.1 U14.11 U16.11 | length 360.6
  L1 w6: U16.11@2169.53,969.13 2171.56,967.1 2181.9,967.1 2190,959 v2(2190,958) ; U14.11@2444,954 2444,932 v2(2458,918)
  L6 w6: v2@2191,959 2214.49,959 2225.49,970 TP35.1@2230,970 2353,970 2363,960 2416,960 v2(2458,918)
IMU_CS: R63.1 TP30.1 U14.12 U16.12 | length 600.4
  L1 w6: U16.12@2175.71,995 U16.12@2176.02,995.32 2180.75,995.32 2184.64,991.43 2184.64,986.7 2188.34,983 2228,983 2235,990 2235,1040.21 2242,1047.21 v2@2242,1052 ; U14.12@2450.93,985.32 2499.68,985.32 R63.1@2504.68,980.32 ; v2(2496,937) 2496,972.8 2503.2,980 R63.1@2507,980
  L6 w6: v2(2240,1049) 2252,1061 2329,1061 2339,1051 2451.49,1051 2455,1047.49 2455,1018 TP30.1@2503,970 ; v2(2496,937) 2505,946 TP30.1@2505,970
IMU_INT2: TP33.1 U14.9 U16.9 | length 424.4
  L1 w6: U16.9@2130.16,969.13 2130.16,935.84 2154,912 v2(2154,903) ; v2(2375,914) 2381,914 2405.16,938.16 U14.9@2405.16,959.23
  L6 w6: TP33.1@2117,907 2119.49,907 2123.49,903 v2(2154,903) ; v2@2153,902 v2(2154,903) ; v2(2375,914) 2354,914 2328,940 2191,940 v2(2154,903)
JOY_SW1_J: SW4.1 U21.V2 | length 766.4
  L1 w3: v2(819.24,574.24) 880.76,574.24 936,519 952.72,519 963.62,508.1 971.42,508.1 972.94,509.62 975.42,509.62 U21.V2@987.2,497.84
  L3-SIG w3: SW4.1@607.05,195 775,195 819.24,239.24 v2(819.24,574.24)
JOY_SW2_J: SW5.1 U21.W2 | length 363.4
  L1 w3: v2(942,478) 952,488 977.36,488 U21.W2@987.2,478.15
  L4-SIG w5: v2(942,478) 942,260.05 SW5.1@1007.05,195
LED0_B_J: Q11.1 R84.2 U21.F19 | length 405.5
  L1 w3: Q11.1@1454.37,975 1454.37,1017.37 v2(1455,1018)
  L6 w3: R84.2@1454.37,985.43 1455,986.06 v2(1455,1018)
  L6 w5: v3(1321.85,734.06) 1346.6,758.81 1346.6,827.6 1389,870 1389,920.57 1402.72,934.28 1442.28,934.28 1454.37,946.37 R84.2@1454.37,985.43
LED0_G_J: Q10.1 R83.2 U21.T1 | length 1186.9
  L1 w5: Q10.1@1564.37,1025 1564.8,1025.43 v2(1592.43,1025.43)
  L6 w5: v3(967.52,537.2) 967.52,592.52 1025,650 1025,715 1118,808 1118,873 1130,885 1237,885 1256,866 1330,866 1371,907 1371,1047 1425,1101 1568,1101 1598,1071 1598,1031 v2(1592.43,1025.43) R83.2@1564.37,1025.43
LED0_R_J: Q9.1 R81.2 U21.D18 | length 593
  L1 w3: U21.D18@1302.16,773.42 1311.74,783 1329.2,783 1353,806.8 1353,820 1365.48,832.48 1643.48,832.48 1676,865 1676,978.37 Q9.1@1674.37,980 ; Q9.1@1674,980 Q9.1@1674.37,980 ; v2(1703,980) Q9.1@1674.37,980
  L6 w3: R81.2@1674.37,980.43 1702.57,980.43 v2(1703,980)
LFXO_N: R111.2 U3.V17 Y2.1 | length 524.2
  L1 w3: U3.V17@2542.8,1532.52 2553,1522.32 2553,1516.79 ; 2552.98,1516.77 2552.98,1494.02 2617,1430 2617,1360 2704,1273 2738,1273 2739.76,1274.76 2739.76,1296.5 2743.26,1300 Y2.1@2746,1300
  L1 w6: Y2.1@2762,1318 2762,1265 2781.31,1245.69 R111.2@2833,1245.69
LFXO_P: U3.W17 Y2.2 | length 428.9
  L1 w3: U3.W17@2542.8,1512.84 2542.8,1489.2 2610,1422 2610,1356 2728,1238 2755,1238 2763,1230 Y2.2@2763,1191
LFXO_P_J: R111.1 TP53.1 U21.W17 | length 3834.7
  L1 w5: U21.W17@1282.48,478.15 1258.33,454 1234,454 1218,438 v2(1218,307) 1272,253 1472,253 1582,363 1582,464 v4(1629,511) ; R111.1@2833,1206.32 2901.31,1206.32 2946,1251 3154,1251 v4(3155,1252)
  L3-SIG w5: v4(1629,511) 1856,511 1979,388 2695,388 2717,366 v4(3180,366)
  L4-SIG w5: v4(3155,1252) 3181,1226 3181,367 v4(3180,366)
  L6 w5: v2(1218,307) 1220.87,304.13 1229.87,304.13 1244,290 1293,290 1303,300 TP53.1@1303,372 ; TP53.1@1301,372 TP53.1@1303,372 ; TP53.1@1301,375 1303,373 TP53.1@1303,372
LINE_OUT_L: C61.2 R56.1 TP27.1 U11.16 | length 340.6
  L1 w8: C61.2@758.72,1896.31 758.72,1876.28 766,1869 766,1857 R56.1@768,1855 ; C61.2@760,1896.31 v2(760,1932) 760,1965 779,1984 869,1984 879.88,1994.88 U11.16@921.26,1994.88
  L6 w8: TP27.1@755,1983 755,1940.25 760,1935.25 v2(760,1932)
LINE_OUT_R: C62.2 R57.1 TP26.1 U11.18 | length 269
  L1 w6: R57.1@855,1847 855,1923 876,1944 955,1944 960.63,1949.63 U11.18@960.63,1971.26
  L6 w6: TP26.1@837,1981 838,1981 v1(876,1943)
MCAM_I2C: J10.34 J12.34 R71.1 R75.2 | length 543.1
  L1 w8: R75.2@4205.69,768 4206.69,767 R71.1@4206.69,714 4208.65,712.03 4278.87,712.03 J10.34@4314.17,676.73 4337.73,676.73 v1(4349,688)
  L4-SIG w8: v1(4281,425) 4317,461 4317,656 v1@4348,687
  L6 w8: v1@4280,423 v1@4281.5,424.5 ; v1(4281,425) v1@4281.5,424.5 ; J12.34@4314.17,427.01 4284.01,427.01 v1@4281.5,424.5
MIPI_CSI_0_N: J10.5 J12.5 TP43.1 U3.V14 | length 3686.4
  L1 w3.2: U3.V14@2483.74,1532.52 2485.01,1531.25 2485.01,1525.03 2493.9,1516.14 2493.9,1500.21 2493,1499.31 2493,1465 2525,1433 2525,1112 2571.05,1065.95 2571.05,922.85 2630.5,863.4 2630.5,527.5 2668,490 2835,490 2849,504 v2(2849,508) ; J10.5@4400,613.74 4403.74,613.74 4408.11,618.11 4421.01,618.11 4446.9,644 4554,644 4582,616 4582,510 4560,488 4530.25,488 4529.25,489 4523.7,489 4514,498.7 v2(4514,502)
  L3-SIG w4.2: v2(2849,508) 2850.45,508 2861.25,497.2 3072.8,497.2 3141.8,428.2 3700.72,428.2 3720.12,447.6 4125.1,447.6 v2@4138,460.5 ; v2(4138,461) v2@4138,460.5 ; v2(4514,502) 4513.23,502 4503.83,492.6 4442.6,492.6 4371.2,421.2 4337.12,421.2 4316.92,401 4232,401 4187.8,445.2 4141,445.2 4138,448.2 v2@4138,460.5
  L6 w3.8: TP43.1@4102,469 4102,446.4 4105.6,442.8 4123,442.8 4138,457.8 v2(4138,461) ; J12.5@4400,490 4402.47,487.53 4504.53,487.53 4514,497 v2(4514,502)
MIPI_CSI_0_P: J10.4 J12.4 TP42.1 U3.W14 | length 3683.9
  L1 w3.2: U3.W14@2483.74,1512.84 2483.74,1511.04 2486.9,1507.87 2486.9,1503.11 2486,1502.21 2486,1462.1 2518,1430.1 2518,1109.1 2564.05,1063.05 2564.05,919.95 2623.5,860.5 2623.5,524.6 2665.1,483 2837,483 v2(2851,469) ; J10.4@4400,629.49 4403.74,629.49 4408.11,625.11 4418.11,625.11 4444,651 4556.9,651 4589,618.9 4589,507.1 4562.9,481 4527.35,481 4526.35,482 4523.7,482 4515,473.3 v2(4515,469)
  L3-SIG w4.2: v2(2851,469) 2854,469 2868,483 3066.92,483 3135.92,414 3706.6,414 3726,433.4 4125.1,433.4 4138.5,420 v2(4139,420) 4139,429 4141,431 4181.92,431 4226.12,386.8 4322.8,386.8 4343,407 4377.08,407 4448.48,478.4 4504.83,478.4 4514.23,469 v2(4515,469)
  L6 w3.8: TP42.1@4102,407 4102,429.6 4104.4,432 4127,432 v2(4139,420) ; J12.4@4400,474.25 4402.47,476.73 4507.27,476.73 v2(4515,469)
MIPI_CSI_1_N: J10.29 J12.29 TP41.1 U3.V15 | length 3683.8
  L1 w3.2: U3.V15@2503.43,1532.52 2503.43,1530.72 2505.63,1528.52 2505.63,1527.37 2513,1520 2513,1498 2511.71,1496.71 2511.71,1472.29 2549.95,1434.05 2549.95,1199.05 2684,1065 2684,993.1 2676.9,986 2632,986 2628,982 2628,975 2634,969 2675.9,969 2684,960.9 2684,913 2702,895 2707,895 2709,897 2709,899 2711,901 2714.13,901 2716,899.13 ; 2716,899 2716,898 2719,895 2736,895 2742,901 v2(2742,910) ; v2(4223,650) 4226,650 4238,638 4238,615.1 4247.06,606.04 4250.73,602.37 4306.06,602.37 4310.43,597.99 J10.29@4314.17,597.99
  L3-SIG w4.2: v2(2742,910) 2737.8,910 2726,898.2 2691.12,898.2 2673.8,880.88 2673.8,787.12 2796.12,664.8 3078.88,664.8 3115.2,701.12 3115.2,871 ; 3115.2,871.2 3128,884 3383,884 3416.8,850.2 3416.8,697.12 3449.12,664.8 3623.8,664.8 3657.4,698.4 4006.6,698.4 4022,683 v2(4023,683) 4026.02,686.02 4026.02,693.02 4029,696 4093.92,696 4117.92,672 4228.9,672 4231.9,669 4231.9,660.36 4223,651.46 v2(4223,650)
  L6 w3.8: v2(4023,683) 4023,685.2 4037,699.2 4059.43,699.2 4063.53,695.1 4084,695.1 4088,691.1 TP41.1@4088,666 ; v2(4223,650) 4235,662 4235,677 4231,681 4222,690 4200,690 4185,675 4185,559 4222,522 4240.73,503.27 4311.7,503.27 J12.29@4314.17,505.75
MIPI_CSI_1_P: J10.30 J12.30 TP40.1 U3.W15 | length 3684
  L1 w3.2: U3.W15@2503.43,1512.84 2503.43,1498 2504.71,1496.71 2504.71,1469.39 2542.95,1431.15 2542.95,1196.15 2677,1062.1 2677,996 2674,993 2629.1,993 ; 2629,993 2629.1,993 ; 2631,962 2631.1,962 ; v2(2742,874) 2742,882 2736,888 2699.1,888 2677,910.1 2677,958 2673,962 2631.1,962 ; v2(4255,649) 4245,639 4245,618 4252.01,610.99 4253.63,609.37 4306.06,609.37 4310.43,613.74 J10.30@4314.17,613.74 ; 2629.1,993 2621,984.9 2621,972.1 2631.1,962
  L3-SIG w4.2: v2(2742,874) 2738.95,874 2728.95,884 2697,884 2688,875 2688,793 2802,679 3073,679 3101,707 3101,877 ; 3101,877.08 3122.12,898.2 3388.88,898.2 3431,856.08 ; 3431,856 3431,703 3455,679 3617.92,679 3651.52,712.6 4006.6,712.6 v2@4021,727 ; v2(4021,728) v2@4021,727 ; v2(4255,649) 4255,650.46 4246.1,659.36 4246.1,674.88 4234.78,686.2 4123.8,686.2 4099.8,710.2 4029,710.2 4021,718.2 v2@4021,727
  L6 w3.8: v2(4021,728) 4021,726 4037,710 4063.9,710 4068,705.9 4084,705.9 4088,709.9 TP40.1@4088,735 ; v2(4255,649) 4255,652.8 4245.8,662 4245.8,681.47 4226.47,700.8 4195.53,700.8 4174.2,679.47 4174.2,554.53 4211.2,517.53 4214.36,514.36 4236.25,492.47 4311.7,492.47 J12.30@4314.17,490
MIPI_CSI_C_N: J10.8 J12.8 TP38.1 U3.V16 | length 3685
  L1 w3.2: U3.V16@2523.11,1532.52 2524.38,1531.25 2524.38,1525.03 2533.27,1516.14 2533.27,1500.21 2531.95,1498.89 2531.95,1486.05 2580,1438 2580,1317.28 2720,1177.28 2720,1128 2725,1123 2743,1123 2749,1117.02 2749,1101.1 2741.9,1094 2722,1094 2720,1092 2720,987 2781,926 2781,814.1 2682,715.1 2682,607 2698,591 2741,591 2742.5,592.5 2750.65,592.5 2752.53,594.37 2752.53,596.98 2758,602.45 v2(2758,607) ; J10.8@4400,566.5 4403.74,566.5 4408.11,570.87 4459.77,570.87 4503.9,615 4537,615 4552,600 4552,576 4543,567 4519.5,567 4518.5,568 4512.95,568 4511.08,569.87 4511.08,571.38 4505,577.45 v2(4505,582)
  L3-SIG w4.2: v2(2758,607) 2774.96,590.04 3234,590.04 3258.8,614.84 3258.8,688.88 ; 3258.8,689 3258.8,688.88 ; v2(4505,582) 4500.8,582 4489,570.2 4453.2,570.2 4439,556 4366,556 4332,590 4119.9,590 4104,574.1 4088.4,574.1 4076.5,586 v2(4076,586) 4076,585.5 4064.6,574.1 4036.9,574.1 3994.8,616.2 3922.12,616.2 3895.96,590.04 3410,590.04 3373,627.04 3373,694.88 3353.68,714.2 3284.12,714.2 3258.8,688.88
  L6 w3.8: v2(4076,586) 4077,585 4077,576.9 4081,572.9 4105,572.9 4110,577.9 TP38.1@4110,600 ; J12.8@4400,537.24 4402.47,534.77 4449.77,534.77 4480.8,565.8 4496,565.8 4505,574.8 v2(4505,582)
MIPI_CSI_C_P: J10.7 J12.7 TP37.1 U3.W16 | length 3683.2
  L1 w3.2: U3.W16@2523.11,1512.84 2523.11,1511.04 2526.27,1507.87 2526.27,1503.11 2524.95,1501.79 2524.95,1483.15 2573,1435.1 2573,1314.38 2713,1174.38 2713,1125.1 2722.1,1116 2740,1116 ; 2740.13,1116 2742,1114.13 2742,1104 2739,1101 2719.1,1101 2713,1094.9 2713,984.1 2774,923.1 2774,817 2675,718 2675,604.1 2695.1,584 2743.9,584 2745.4,585.5 2750.65,585.5 2752.53,583.63 2752.53,582.02 2759,575.55 v2(2759,571) ; J10.7@4400,582.24 4403.74,582.24 4408.11,577.87 4456.87,577.87 4501,622 4539.9,622 4559,602.9 4559,573.1 4545.9,560 4516.6,560 4515.6,561 4512.95,561 4511.08,559.13 4511.08,557.62 4505,551.55 v2(4505,547)
  L3-SIG w4.2: v2(2759,571) 2763.28,571 2768.12,575.84 3239.88,575.84 3273,608.96 3273,683 3290,700 3347.8,700 3358.8,689 3358.8,621.16 3404.12,575.84 3901.84,575.84 3928,602 3988.92,602 4031.02,559.9 4064.6,559.9 4076.5,548 v2(4077,548) 4077,548.5 4088.4,559.9 4109.88,559.9 4125.78,575.8 4326.12,575.8 4360.12,541.8 4444.88,541.8 4459.08,556 4491.72,556 4500.72,547 v2(4505,547)
  L6 w3.8: v2(4077,548) 4077,558.1 4081,562.1 4105,562.1 4110,557.1 TP37.1@4110,535 ; J12.7@4400,521.5 4402.47,523.97 4454.24,523.97 4485.27,555 4497,555 v2(4505,547)
MIPI_DSI_0_N: J18.18 TP58.1 U3.V11 | length 1909.1
  L1 w3.2: U3.V11@2425.76,1531.45 U3.V11@2424.68,1532.52 2424.68,1562.68 2432.06,1570.06 2432.68,1570.06 2435.62,1573 v3(2438,1573) ; v2(3904,1722) 3904,1713 3908,1709 3921.71,1709 3938,1692.71 3947.73,1692.71 3949.6,1694.59 3949.6,1694.66 3954,1699.06 J18.18@3965,1699.06
  L3-SIG w4.2: v3(2438,1573) 2440.11,1573 2444.01,1569.1 2453,1569.1 2543.9,1660 2692,1660 2736.2,1704.2 2787,1704.2 2896.56,1813.76 3437,1813.76 3446.8,1823.56 3446.8,1875.88 ; 3446.8,1876 3446.8,1875.88 ; v2(3904,1722) 3900.55,1722 3890.75,1712.2 3667.88,1712.2 3566.32,1813.76 3531,1813.76 3522,1822.76 3522,1874.08 3500.88,1895.2 3466.12,1895.2 3446.8,1875.88
  L6 w3.8: TP58.1@3879,1741 v2@3904,1716
MIPI_DSI_0_P: J18.17 TP59.1 U3.W11 | length 1907.1
  L1 w3.2: U3.W11@2424.68,1512.84 2434.85,1523 2434.85,1544.73 2440,1549.88 v3(2440,1551) ; v2(3904,1690) 3904,1698 3908,1702 3918.81,1702 3935.1,1685.71 3947.73,1685.71 3949.6,1683.84 3949.6,1683.77 3954,1679.37 J18.17@3965,1679.37
  L3-SIG w4.2: v3(2440,1551) 2442.11,1551 2446.01,1554.9 2458.88,1554.9 2549.78,1645.8 2697.88,1645.8 2742.08,1690 2792.88,1690 2902.44,1799.56 3442.88,1799.56 3461,1817.68 3461,1869 ; 3461,1870 3472,1881 3495,1881 3507.8,1868.2 3507.8,1816.88 3525.12,1799.56 3560.44,1799.56 3662,1698 3857,1698 3860,1695 3860,1691 3863,1688 3871,1688 3876,1693 3876,1695 3879,1698 3891.72,1698 3899.72,1690 v2(3904,1690)
  L6 w3.8: TP59.1@3879,1675 3892.13,1688.13 3902.13,1688.13 v2(3904,1690)
MIPI_DSI_1_N: J18.12 TP62.1 U3.V9 | length 1900.6
  L1 w3.2: v3@2363,1571 2363,1564 2365,1562 2377.08,1562 2383.05,1556.02 2383.05,1543.14 2382.15,1542.24 2382.15,1537.48 2385.32,1534.32 U3.V9@2385.32,1532.52 ; v2(3922,1589) 3922,1578.6 3926,1574.6 3947.73,1574.6 3949.6,1576.48 3949.6,1576.54 3954,1580.94 J18.12@3965,1580.94
  L3-SIG w4.2: v3(2363.01,1571.81) 2364.97,1571.81 2369.37,1567.41 2381.2,1567.41 2393.04,1555.57 2393.04,1468.04 2403.88,1457.2 2475.88,1457.2 2489.08,1444 2842,1444 2886,1488 3398,1488 3427,1517 3635,1517 3687.2,1569.2 3801.88,1569.2 3826.88,1544.2 3844.2,1544.2 3877.6,1577.6 3881.54,1577.6 3884,1580.06 3884,1583 3887,1586 3894,1586 3897,1583 3897,1581.6 3901,1577.6 3910.1,1577.6 3921.5,1589 v2(3922,1589)
  L6 w3.8: TP62.1@3890,1595 3911.67,1595 3918.67,1588 v2@3921,1588
MIPI_DSI_1_P: J18.11 TP63.1 U3.W9 | length 1900.6
  L1 w3.2: v3@2363,1548 2363,1553 2365,1555 2374.18,1555 2376.05,1553.13 2376.05,1546.04 2375.15,1545.14 2375.15,1529.22 2384.04,1520.33 2384.04,1514.11 U3.W9@2385.32,1512.84 ; v2(3921,1552) 3921,1562.6 3926,1567.6 3947.73,1567.6 3949.6,1565.73 3949.6,1565.66 3954,1561.26 J18.11@3965,1561.26
  L3-SIG w4.2: v3(2363.01,1548.81) 2364.97,1548.81 2369.37,1553.21 2375.31,1553.21 2378.84,1549.69 2378.84,1462.16 2398,1443 2470,1443 2483.2,1429.8 2847.88,1429.8 2891.88,1473.8 3403.88,1473.8 3432.88,1502.8 3640.88,1502.8 3693.08,1555 3796,1555 3821,1530 3850.08,1530 3883.48,1563.4 3910.1,1563.4 3921,1552.5 v2(3921,1552)
  L6 w3.8: TP63.1@3895,1533 3897,1533 3912.9,1548.9 3913.52,1548.9 3919,1554.38 v2@3919,1555
MIPI_DSI_C_N: J18.15 TP60.1 U3.V10 | length 1907.3
  L1 w3.2: U3.V10@2405,1532.52 2415,1522.52 2415,1509.05 2420.74,1503.31 2422.73,1503.31 v3(2429,1497) ; v2(3920.1,1651.29) 3923.32,1648.08 3923.32,1641.51 3926.18,1638.65 3931.73,1638.65 3936.72,1633.66 3947.73,1633.66 3949.6,1635.53 3949.6,1635.6 3954,1640 J18.15@3965,1640
  L3-SIG w4.2: v3(2429,1497) 2429,1494.89 2426,1491.89 2426,1486 2429,1483 2494,1483 2497.8,1479.2 2586.12,1479.2 2609.12,1502.2 2752.88,1502.2 2759.08,1496 2816,1496 2858.2,1538.2 3302.2,1538.2 3402.2,1638.2 3474,1638.2 3482.8,1647 3482.8,1665.88 3502.12,1685.2 3528.68,1685.2 3546,1667.88 ; 3546,1668 3546,1667.88 ; v2(3920.1,1651.29) 3918.79,1651.29 3909.74,1642.25 3899.05,1642.25 3895,1638.2 3556,1638.2 3546,1648.2 3546,1667.88
  L6 w3.8: v2(3920.1,1651.29) 3935.49,1635.9 4042.27,1635.9 4044.5,1638.13 4044.5,1660.5 TP60.1@4044,1661
MIPI_DSI_C_P: J18.14 TP61.1 U3.W10 | length 1905.3
  L1 w3.2: U3.W10@2405,1512.84 2405,1480 v3(2406,1479) ; v2(3920,1619) 3923.21,1622.21 3923.21,1628.68 3926.18,1631.65 3928.83,1631.65 3933.82,1626.66 3947.73,1626.66 3949.6,1624.78 3949.6,1624.71 3954,1620.31 J18.14@3965,1620.31
  L3-SIG w4.2: v3(2406,1479) 2407.04,1477.96 2413.96,1477.96 2423.12,1468.8 2488.12,1468.8 2491.92,1465 2592,1465 2615,1488 2747,1488 2753.2,1481.8 2821.88,1481.8 2864.08,1524 3308.08,1524 3408.08,1624 3479.88,1624 3497,1641.12 3497,1660 3508,1671 3522.8,1671 3531.8,1662 3531.8,1642.32 3550.12,1624 3872,1624 3876.26,1619.74 3879.74,1619.74 3884,1624 3900.88,1624 3904.93,1628.05 3909.64,1628.05 3918.69,1619 v2(3920,1619)
  L6 w3.8: v2(3920,1619) 3923.1,1622.1 3935.08,1622.1 3938.08,1625.1 4042.27,1625.1 4045,1622.37 TP61.1@4045,1600
NetC2_2: C2.2 R1.2 S1.1 U1.5 | length 414.6
  L1 w5: R1.2@1360,1410.63 R1.2@1362.72,1407.91
  L1 w20: C2.2@1362.72,1350 U1.5@1410,1350 ; R1.2@1362.72,1407.91 1362.72,1175.28 v2(1400,1138)
  L6 w20: S1.1@1339,1106.3 1339,1113.17 1363.83,1138 v2(1400,1138)
NetC5_2: C5.2 R7.2 S2.1 U2.5 | length 454.5
  L1 w20: C5.2@997,1480 997,1458 v2(1016,1439) ; C5.2@997.72,1480 995.51,1482.2 995.51,1490.49 969,1517 969,1560 976,1567 R7.2@999,1567 ; C5.2@999,1485 U2.5@1055,1485
  L6 w20: 799,1420 825,1420 844,1439 v2(1016,1439)
NetC24_1: C24.1 FB6.2 TP15.1 U3.B1 | length 263.1
  L1 w8: C24.1@2124,1898 2125.73,1896.27 FB6.2@2125.73,1853 ; FB6.2@2127.52,1847.48 v4@2176,1847.48 ; v4(2176,1847) v4@2176,1847.48 ; U3.B1@2227.84,1847.48 v4@2176,1847.48
  L6 w8: v4(2176,1847) 2211,1882 2211,1921.82 2194,1938.82 TP15.1@2194,1942
NetC35_2: C35.2 R99.1 | length 71.8
  L6 w3: R99.1@2367,1605 2369.3,1607.3 2383.3,1607.3 2386,1610 2404,1610 2412.01,1618.01 2412.01,1624.3 C35.2@2422.72,1635
NetC53_2: C53.2 FB10.1 Q7.1 Q7.2 Q7.5 Q7.6 R42.2 | length 390.6
  L1 w10: C53.2@1150,2384 1150,2430 R42.2@1150.32,2430.32 ; R42.2@1150.32,2430 Q7.5@1209.13,2430 ; Q7.6@1209.13,2392.6 1212,2395.46 Q7.5@1212,2426 ; Q7.5@1212,2430 Q7.2@1311.5,2430 ; Q7.1@1311.5,2392.6 Q7.2@1311.5,2427.5 ; Q7.1@1322,2385 1325,2385 1326.18,2383.82 1326.18,2380.82 1342,2365 FB10.1@1428.27,2365
NetC58_2: C58.2 R54.2 | length 68.1
  L1 w6: C58.2@508,2538 510,2540 R54.2@575.31,2540
NetC59_2: C59.2 R55.2 | length 42.4
  L1 w5: R55.2@670,2260 670,2219 C59.2@671,2218
NetC61_1: C61.1 R58.1 | length 45.7
  L1 w8: R58.1@720,1852 723.28,1855.28 C61.1@723.28,1896.31
NetC62_1: C62.1 R59.1 | length 35.8
  L1 w8: R59.1@812,1857 812.17,1857 813,1857.83 813,1870 814.48,1871.48 814.48,1889.48 C62.1@816,1891
NetC63_1: C63.1 U11.10 | length 109.6
  L1 w6: C63.1@836,2147 836,2146.28 844.2,2138.08 846.92,2138.08 895.63,2089.37 U11.10@921.26,2089.37
NetC63_2: C63.2 U11.8 | length 158
  L1 w6: C63.2@831,2181 931,2181 944.88,2167.12 U11.8@944.88,2128.74
NetC69_2: C69.2 U11.21 | length 91.4
  L1 w6: U11.21@1007.87,1971.26 1007.87,1909.13 1013,1904 C69.2@1013,1882
NetC70_2: C70.2 U11.20 | length 99.4
  L1 w6: C70.2@970,1881 970,1903 992.13,1925.13 U11.20@992.13,1971.26
NetC71_2: C71.2 U11.11 | length 97.5
  L1 w6: C71.2@833,2096 856,2096 878.38,2073.62 U11.11@921.26,2073.62
NetC72_2: C72.2 U11.12 | length 95.7
  L1 w6: C72.2@831,2049 850,2049 861,2060 905,2060 906.19,2058.81 920.32,2058.81 U11.12@921.26,2057.87
NetC114_2: C114.2 R102.1 | length 49.9
  L6 w5: C114.2@1207.72,530 1224.32,513.4 R102.1@1224.32,487
NetC125_2: C125.2 Q8.1 R44.2 R93.1 | length 213.5
  L1 w10: Q8.1@1374.68,2649.57 1374.68,2729.68 1382,2737 1425,2737 R93.1@1429,2741 ; Q8.1@1375.59,2649.57 C125.2@1450,2649.57
NetC131_2: C131.2 U23.16 | length 274.7
  L1 w10: C131.2@337,489 342,494 342,536 393,587 474,587 491,570 511,570 515,566 515,565.91 523.53,557.37 U23.16@523.53,546.73
NetD1_5: D1.5 D3.5 R2.1 | length 426.7
  L1 w25: R2.1@522,1645 579,1645 593,1631 593,1531.07 ; D3.5@609.21,1380 578,1380 562,1396 562,1438 593,1469 593,1531.07 ; D1.5@640,1534 595.93,1534 593,1531.07
NetD2_A: D2.A R5.2 | length 57
  L1 w10: D2.A@1435.47,1625 1440.31,1629.84 R5.2@1440.31,1680
NetD3_1: D3.1 FB2.2 | length 165.2
  L1 w5: FB2.2@352,1433 417,1433 432.6,1417.4 D3.1@510.79,1417.4
NetD3_6: D3.6 R8.1 | length 75.2
  L1 w5: D3.6@615,1419 615.37,1419.37 R8.1@690,1419.37
NetD4_2: D4.2 R13.2 | length 163.9
  L1 w10: v2(2687,2407) 2697.39,2396.61 2709.93,2396.61 D4.2@2713.27,2393.27
  L6 w10: R13.2@2673,2321 2701,2321 2710,2330 2710,2392 2696.91,2405.09 2688.91,2405.09 v2(2687,2407)
NetD4_3: D4.3 R17.1 | length 68.3
  L1 w10: v2(2695,2454) 2709.27,2439.73 2709.27,2430.73 D4.3@2713.27,2426.73
  L6 w10: R17.1@2674,2478 2674,2473.72 2675.51,2472.2 2676.8,2472.2 v2(2695,2454)
NetD4_4: D4.4 R14.1 | length 180.9
  L1 w10: D4.4@2746.73,2426.73 2798.27,2426.73 v2(2823,2402)
  L6 w10: R14.1@2781,2479 2781,2444 v2(2823,2402)
NetD5_4: D5.4 R96.2 R98.2 | length 153.9
  L1 w3.2: D5.4@465,666 R96.2@516,666 ; v4@502,631 518.31,647.31 R96.2@518.31,667
  L1 w15: v4@502,631 v4@502,631.81 ; R96.2@514.99,664.99 R96.2@516,666
  L6 w3.8: v4(502.32,631) 516.32,631 521.63,636.31 R98.2@521.63,668
  L6 w15: R98.2@518.3,664.67 R98.2@521.63,668
NetD5_5: D5.5 R16.1 | length 194.4
  L1 w15: R16.1@448,856 448,823 423,798 423,725 437.69,710.31 463.9,710.31 D5.5@468.21,706
NetD5_6: D5.6 R95.2 R97.2 | length 166.2
  L1 w3.2: D5.6@466,743 R95.2@519,743 ; v4(499,785) 515,785 521,779 R95.2@521,746
  L1 w15: R95.2@519,738 R95.2@519,743
  L6 w3.8: v4(499,785) 506,785 517.31,773.69 R97.2@517.31,746
NetD6_2: D6.2 R20.2 | length 114.1
  L1 w10: D6.2@3198,2394 3198,2367 v2(3209,2356)
  L6 w10: R20.2@3165,2305 3170.83,2310.83 3170.83,2321.83 3205,2356 v2(3209,2356)
NetD6_3: D6.3 R23.1 | length 76.2
  L1 w10: v2(3197,2476) 3197,2428 D6.3@3198.27,2426.73
  L6 w10: R23.1@3171,2477 3172,2476 v2(3197,2476)
NetD6_4: D6.4 R21.1 | length 89.9
  L1 w10: D6.4@3231.73,2426.73 3231.73,2475.03 3235,2478.29 v2(3235,2481)
  L6 w10: v2@3236,2480 R21.1@3270.31,2480
NetD9_2: D9.2 R79.2 | length 176.7
  L1 w3: v2(1501,884) 1527.54,884 D9.2@1528.27,883.27
  L6 w3: v2(1501,884) 1579,884 1615.43,920.43 R79.2@1635,920.43
NetD9_3: D9.3 R82.1 | length 84.3
  L1 w3: v2(1500,924) 1507.27,916.73 D9.3@1528.27,916.73
  L6 w3: R82.1@1454.68,905.43 1476.43,905.43 1490.25,919.25 1490.65,919.25 1495.4,924 v2(1500,924)
NetD9_4: D9.4 R80.1 | length 102.2
  L1 w3: D9.4@1563,916 1585,916 1594,925 v2(1594,961)
  L6 w3: R80.1@1564.37,965.43 1589.57,965.43 v2(1594,961)
NetD10_2: D10.2 L5.2 U22.1 | length 268.2
  L1 w10: L5.2@3498,1101 L5.2@3504,1107 ; L5.2@3505.25,1162.75 L5.2@3508,1160
  L1 w20: L5.2@3504,1107 D10.2@3630,1107 ; L5.2@3505.25,1162.75 U22.1@3505.25,1292.6
NetJ6_1: J6.1 R40.2 | length 135.3
  L1 w10: R40.2@3379.69,2850 J6.1@3515,2850
NetJ6_3: J6.3 R41.2 | length 123.3
  L1 w6: J6.3@3717,2845 R41.2@3840.31,2845
NetJ11_1: J11.1 R73.1 | length 323.9
  L1 w10: R73.1@3719.69,495 3719.69,467.32 3886,301 J11.1@3886,240
NetQ1_3: Q1.3 R13.1 | length 76.2
  L1 w10: v2(2601,2333) 2601.86,2333 2611.86,2323 Q1.3@2634,2323
  L6 w10: v2(2601,2333) 2613.15,2320.85 R13.1@2635,2320.85
NetQ2_3: Q2.3 R14.2 | length 57.4
  L1 w10: Q2.3@2816,2469 2824.82,2460.18 2837.82,2460.18 v2(2839,2459)
  L6 w10: R14.2@2819.37,2480 2819.37,2478.03 2825.2,2472.2 2827.17,2472.2 2839,2460.37 v2(2839,2459)
NetQ3_3: Q3.3 R17.2 | length 69.3
  L1 w10: v2(2596,2480) Q3.3@2631,2480
  L6 w10: v2(2596,2480) R17.2@2630.31,2480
